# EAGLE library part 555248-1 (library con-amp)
AMP connector
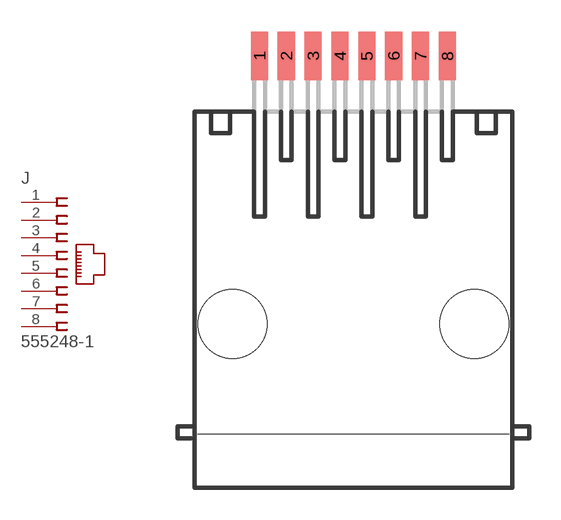
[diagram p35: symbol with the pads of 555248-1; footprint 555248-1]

Designator prefix J

## 555248-1 (MPN: 5555248-1; OC_FARNELL: 1764713; OC_NEWARK: 46P3270)  [555248-1]
1  1  pas
2  2  pas
3  3  pas
4  4  pas
5  5  pas
6  6  pas
7  7  pas
8  8  pas

## Footprint 555248-1 (pad centres in mm)
Modular Jack with Panel Stops
smd 0.813 x 2.286: 1 -4.445,11.533; 2 -3.175,11.533; 3 -1.905,11.533; 4 -0.635,11.533; 5 0.635,11.533; 6 1.905,11.533; 7 3.175,11.533; 8 4.445,11.533
hole 3.251 at -5.715,-1.143
hole 3.251 at 5.715,-1.143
